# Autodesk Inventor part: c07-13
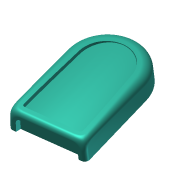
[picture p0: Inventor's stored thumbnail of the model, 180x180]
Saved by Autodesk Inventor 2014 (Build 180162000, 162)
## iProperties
Created: 2010-12
Part Number: c07-13
Material: Generic
Document SubType Name: Modeling
Designer: Thom Tremblay
Density: 1 g/cm^3
Appearance: Smooth - Aqua
Author: Thom Tremblay
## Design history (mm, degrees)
sketch "Sketch1"
  geometry: L1 (-25, 0)-(25, 0); L2 (25, 0)-(25, 80); L3 (25, 80)-(-25, 80); L4 (-25, 80)-(-25, 0); 2 further points
  constraints: 8 end point, 2 parallel, 1 coincident, 1 horizontal, 1 midpoint, 1 perpendicular
  dimensions: "d0" = 50 distance of L3.end L2.end; "d1" = 80 distance of L2.end L1.end
extrude "Extrusion1" new body sketch "Sketch1" distance "d2" = 15; taper "d3" = 0 deg
feature "FaceDraft1" dims angle "d4" = -2 deg
fillet "Fillet1"
fillet "Fillet2" dims "d5" = 8, "d6" = 8, "d7" = 8, "d8" = 8, "d9" = 8, "d10" = 8, "d11" = 3, "d12" = 3, "d13" = 3, "d14" = 6, "d15" = 5
sketch "Sketch2"
  geometry: L1 (5.522, 12)-(38.474, 12) reference; L2 (0, 0)-(43.996, 0) reference; L3 (41.757, 6.83)-(41.995, 0); L4 (41.925, 2)-(2.071, 2); L5 (2.001, 0)-(2.24, 6.83); L6 (5.522, 10)-(38.474, 10); A1 r 5.284 centre (38.474, 6.716) between (43.755, 6.9) and (38.474, 12) reference; A2 r 5.284 centre (5.522, 6.716) between (5.522, 12) and (0.241, 6.9) reference; A3 r 3.284 centre (38.474, 6.716) between (41.757, 6.83) and (38.474, 10); A4 r 3.284 centre (5.522, 6.716) between (5.522, 10) and (2.24, 6.83); 1 further point
  constraints: 8 end point, 4 point on circle, 4 point on line, 2 centre point, 1 other
  dimensions: "d16" = 2 radial gap between concentric circles of A2 A4
extrude "Extrusion2" cut sketch "Sketch2" distance "d17" = 3; taper "d18" = 0 deg
feature "FaceDraft2" dims angle "d19" = 15 deg
sketch "Sketch3" dims "d20" = 2.5
  geometry: L1 (16.476, 3)-(-16.476, 3) reference; L2 (16.476, 5.5)-(-16.476, 5.5); 9 further points
  constraints: 2 end point, 2 parallel, 1 horizontal alignment, 19 other
extrude "Extrusion3" cut sketch "Sketch3" distance "d21" = 3; taper "d22" = 0 deg
feature "FaceDraft3" dims angle "d23" = 10 deg
workplane "Work Plane1"
sketch "Sketch4"
  geometry: L1 (41.1, -1.222)-(41.476, -12) reference; L2 (41.476, -12)-(-8.524, -12) reference; L3 (-8.524, -12)-(-8.147, -1.222) reference; L4 (-3.776, 3)-(-1.272, 3) reference; L5 (-0.743, 0)-(33.695, 0) reference; L6 (34.225, 3)-(36.728, 3) reference; L7 (-11.024, -1.804)-(43.976, -1.804); A1 r 90 centre (16.476, -87.5) between (43.976, -1.804) and (-11.024, -1.804); 2 further points
  constraints: 2 end point, 2 point on circle, 1 centre point, 1 midpoint, 1 parallel, 1 vertical alignment, 4 other
  dimensions: "d25" = 90 radius of A1; "d26" = 14.5 distance edge to line of A1 L2; "d27" = 55 distance of L7.start L7.end
extrude_surface "ExtrusionSrf1" sketch "Sketch4" dims "d28" = 86, "d29" = 0
feature "Replace Face1"
body "Solid1"
body "Srf1"
node "Project Cut Edges1"
